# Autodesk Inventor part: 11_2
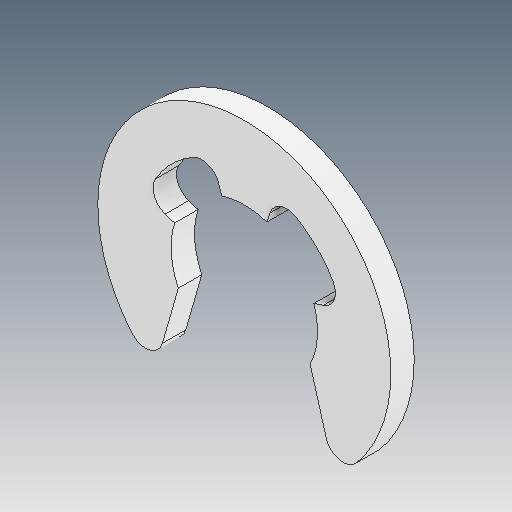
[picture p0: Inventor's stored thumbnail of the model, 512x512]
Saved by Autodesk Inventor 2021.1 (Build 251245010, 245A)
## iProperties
Created: 2021-06
Part Number: 11_2
Material: Ogólny
Document SubType Name: Modeling
Designer: user
Density: 1 g/cm^3
Appearance: Domyślna
Author: user
Revision Number: ÈÎºÎ
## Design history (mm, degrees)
feature "ÊäÈë1"
node "Bryła1"
